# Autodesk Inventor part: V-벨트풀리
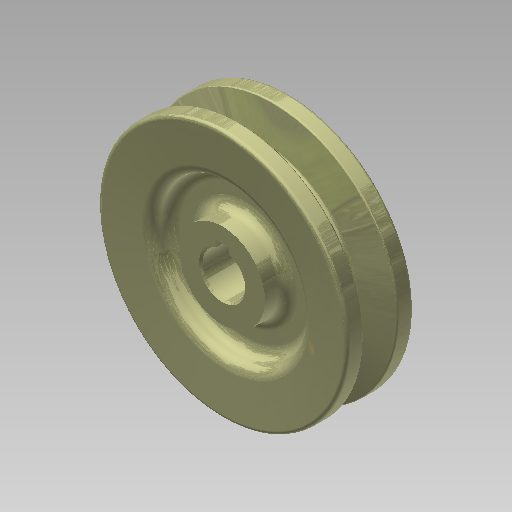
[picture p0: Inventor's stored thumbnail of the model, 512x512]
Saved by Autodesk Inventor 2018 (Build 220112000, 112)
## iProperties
Created: 2016-08
Part Number: V-벨트풀리
Material: 일반
Document SubType Name: Modeling
Designer: mduedu
Density: 1 g/cm^3
Mass: 44.0848 g
Surface Area: 158.218 cm^2
Volume: 44.0848 cm^3
Appearance: 알루미늄 - 평지
Author: mduedu
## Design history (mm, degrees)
sketch "스케치1"
  geometry: L1 (0, 9.5)-(0, -9.5); L2 (0, 9.5)-(35, 9.5); L3 (35, 9.5)-(35, 4.825); L4 (35, 4.825)-(26, 2.074); L5 (26, 2.074)-(26, 0); L6 (0, 0)-(26, 0); L7 (0, -9.5)-(35, -9.5); L8 (35, -9.5)-(35, -4.825); L9 (35, -4.825)-(26, -2.074); L10 (26, -2.074)-(26, 0); L11 (32.3, 9.5)-(32.3, -9.5); 3 further points
  constraints: 22 end point, 6 point on line, 4 perpendicular, 3 symmetric about line, 1 coincident, 1 horizontal alignment, 1 midpoint, 1 parallel, 1 vertical
  dimensions: "d0" = 19 distance of L1.start L1.end; "d2" = 70 diameter of L8 L1; "d4" = 6.3 distance between parallel lines of L10 L11; "d5" = 2.7 distance between parallel lines of L11 L8; "d6" = 8 distance of point (32.3, -4) point (32.3, 4); "d7" = 34 deg angle of L9 L4
revolve "회전1" sketch "스케치1" stored, may be unused: angle "d8" = 90 deg
sketch "스케치2"
  geometry: L1 (-2, 0)-(2, 0); L2 (2, 0)-(2, 7.8); L3 (2, 7.8)-(-2, 7.8); L4 (-2, 7.8)-(-2, 0); C1 r 6 at (0, 0); 2 further points
  constraints: 8 end point, 2 coincident, 2 parallel, 1 centre point, 1 horizontal, 1 midpoint, 1 perpendicular
  dimensions: "d9" = 12 diameter of C1; "d11" = 4 distance of L2.end L3.end; "d12" = 7.8 distance of L1.end L2.end
extrude "돌출1" cut sketch "스케치2" extent not by distance; stored distance "d13" = 10; taper "d14" = 0 deg
sketch "스케치3"
  geometry: L1 (35, 4.825)-(26, 2.074) reference; L2 (26, 2.074)-(26, -2.074) reference; L3 (0, 0)-(26, 0); L4 (35, 9.5)-(35, 4.825) reference; L5 (-35, 9.5)-(35, 9.5) reference; L6 (35, 9.5)-(21, 8.275); L7 (21, 8.275)-(21, 3); L8 (21, 3)-(12, 3); L9 (12, 3)-(12, 9.5); L10 (0, 9.5)-(0, -9.5); L11 (5.657, -9.5)-(-6, -9.5) reference; L12 (12, 9.5)-(35, 9.5)
  constraints: 14 end point, 3 midpoint, 2 perpendicular, 2 point on line, 1 collinear, 1 horizontal, 1 parallel
  dimensions: "d15" = 3 distance between parallel lines of L3 L8; "d17" = 42 diameter of L7 L10; "d18" = 24 diameter of L9 L10; "d31" = 5 deg angle of L6 L5
revolve "회전2" sketch "스케치3" stored, may be unused: angle "d19" = 90 deg
fillet "모깎기1" dims "d20" = 0.5, "d21" = 1, "d22" = 1
fillet "모깎기2" dims "d23" = 3
fillet "모깎기3" dims "d24" = 3
fillet "모깎기4" dims "d25" = 3
chamfer "모따기1" distance "d26" = 0.5; stored, may be unused: second distance "d27" = 2, angle "d28" = 45 deg
node "솔리드1"
mirror "대칭1"
